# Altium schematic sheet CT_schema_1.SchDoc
size 381 x 258 mm
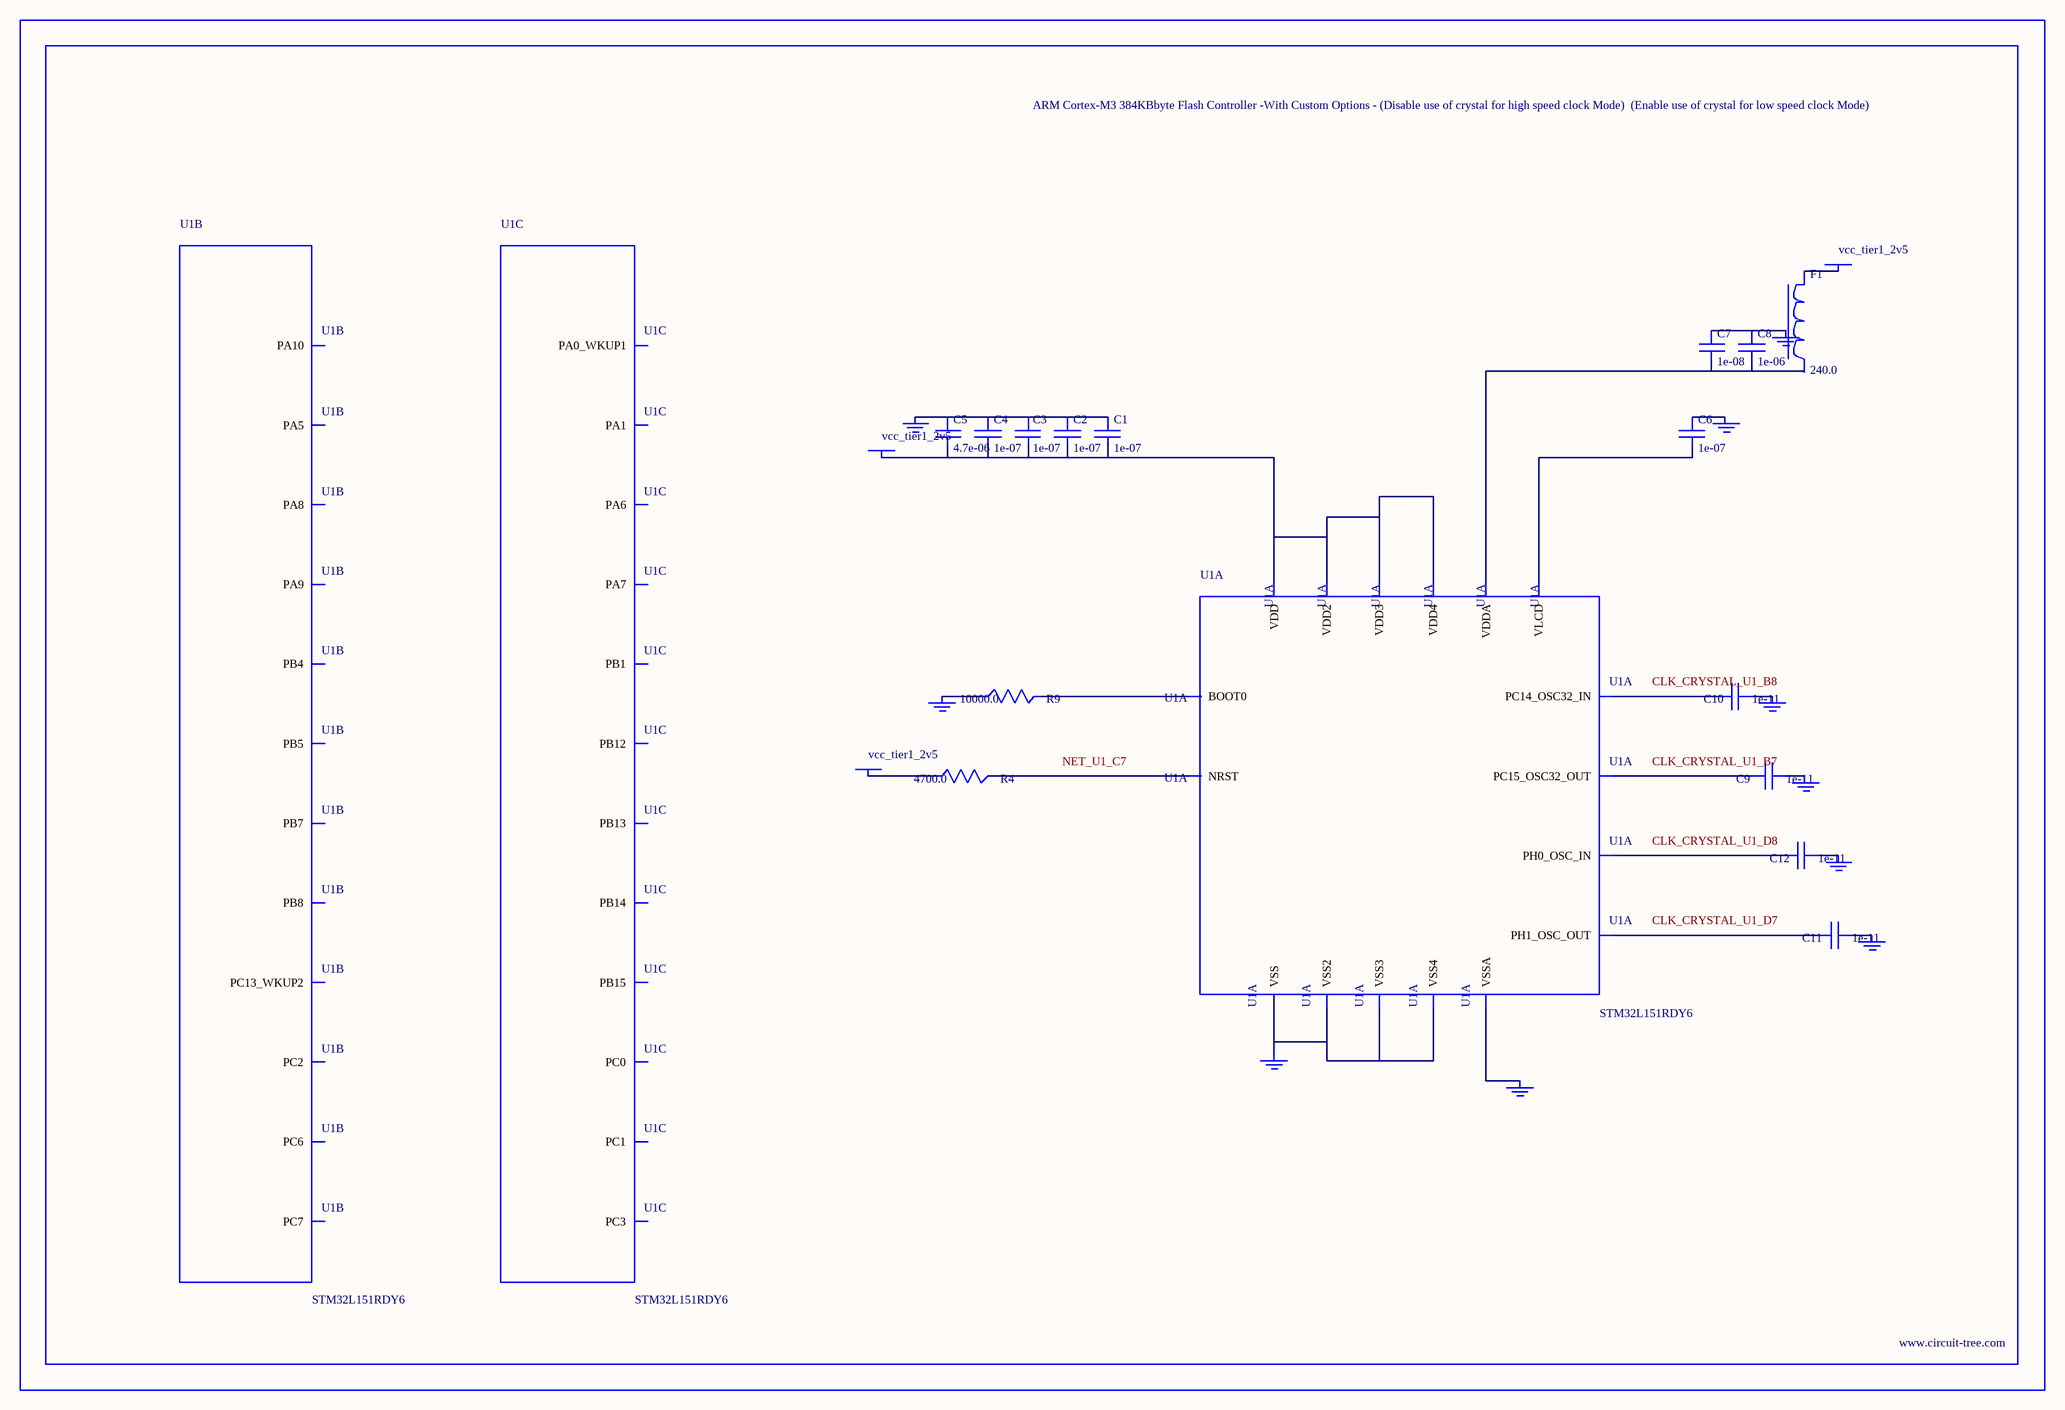
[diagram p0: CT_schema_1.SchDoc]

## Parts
BORDER0  (no value)
C1  1e-07  [C0603]
C2  1e-07  [C0603]
C3  1e-07  [C0603]
C4  1e-07  [C0603]
C5  4.7e-06  [C0603]
C6  1e-07  [C0603]
C7  1e-08  [C0603]
C8  1e-06  [C0603]
C9  1e-11  [C0402]
C10  1e-11  [C0402]
C11  1e-11  [C0402]
C12  1e-11  [C0402]
F1  240.0  [L0603]
GND_INSTANCE_0_0  (no value)
GND_INSTANCE_0_1  (no value)
GND_INSTANCE_0_2  (no value)
GND_INSTANCE_0_3  (no value)
GND_INSTANCE_0_4  (no value)
GND_INSTANCE_0_5  (no value)
GND_INSTANCE_0_6  (no value)
GND_INSTANCE_0_7  (no value)
GND_INSTANCE_0_8  (no value)
GND_INSTANCE_0_9  (no value)
POWER_INSTANCE_0_0  vcc_tier1_2v5
POWER_INSTANCE_0_1  vcc_tier1_2v5
POWER_INSTANCE_0_2  vcc_tier1_2v5
R4  4700.0  [R0603]
R9  10000.0  [R0603]
U1  STM32L151RDY6  [WLCSP64]  (parts A,B,C of 8)

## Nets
NetC1_1: C1.1 C2.1 C3.1 C4.1 C5.1 GND_INSTANCE_0_1.0(GND)
NetC1_2: C1.2 C2.2 C3.2 C4.2 C5.2 POWER_INSTANCE_0_1.0(PWR) U1.A1(VDD) U1.A8(VDD2) U1.G6(VDD3) U1.H1(VDD4)
NetC6_1: C6.1 GND_INSTANCE_0_2.0(GND)
NetC6_2: C6.2 U1.C6(VLCD)
NetC7_1: C7.1 C8.1 GND_INSTANCE_0_0.0(GND)
NetC7_2: C7.2 C8.2 U1.G8(VDDA)
NetC9_1: C9.1 GND_INSTANCE_0_4.0(GND)
NetC9_2: C9.2 U1.B7(PC15_OSC32_OUT)
NetC10_1: C10.1 GND_INSTANCE_0_5.0(GND)
NetC10_2: C10.2 U1.B8(PC14_OSC32_IN)
NetC11_1: C11.1 GND_INSTANCE_0_6.0(GND)
NetC11_2: C11.2 U1.D7(PH1_OSC_OUT)
NetC12_1: C12.1 GND_INSTANCE_0_7.0(GND)
NetC12_2: C12.2 U1.D8(PH0_OSC_IN)
NetF1_1: F1.1 POWER_INSTANCE_0_0.0(PWR)
NetGND_INSTANCE_0_3_0: GND_INSTANCE_0_3.0(GND) R9.1
NetGND_INSTANCE_0_8_0: GND_INSTANCE_0_8.0(GND) U1.E7(VSSA)
NetGND_INSTANCE_0_9_0: GND_INSTANCE_0_9.0(GND) U1.A7(VSS) U1.B1(VSS2) U1.F5(VSS3) U1.H2(VSS4)
NetPOWER_INSTANCE_0_2_0: POWER_INSTANCE_0_2.0(PWR) R4.1
NetR4_2: R4.2 U1.C7(NRST)
NetR9_2: R9.2 U1.A6(BOOT0)

Not connected (* = marked no-connect by the designer): F1 2; U1 A5(PB5) B4(PB4) C5(PB7) C8(PC13_WKUP2) D2(PA9) D3(PA10) D5(PB8) D6(PC2) E1(PC6) E2(PC7) E4(PA8) E5(PA5) E6(PA1) E8(PC0) F1(PB15) F2(PB14) F4(PB1) F6(PA0_WKUP1) F7(PC3) F8(PC1) G1(PB13) G2(PB12) G4(PA7) G5(PA6)

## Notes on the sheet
- Labels drawn without touching a wire or pin: CLK_CRYSTAL_U1_B7, CLK_CRYSTAL_U1_B8, CLK_CRYSTAL_U1_D7, CLK_CRYSTAL_U1_D8, NET_U1_C7

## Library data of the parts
BORDER0 = BORDER_PAGE0
C1-C4 C6 = 06035C104K4Z2A
C5 = GRM188R6YA475KE15D
C7 = 06035C103K4Z2A
C8 = C0603C105K3RACTU
C9-C12 = C0402C100K3GACTU
F1 = Z0603C241ASMST
GND_INSTANCE_0_0-GND_INSTANCE_0_9 = GND
POWER_INSTANCE_0_0-POWER_INSTANCE_0_2 = PWR
R4 = RC0603JR-074K7L
R9 = RC0603JR-0710KL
